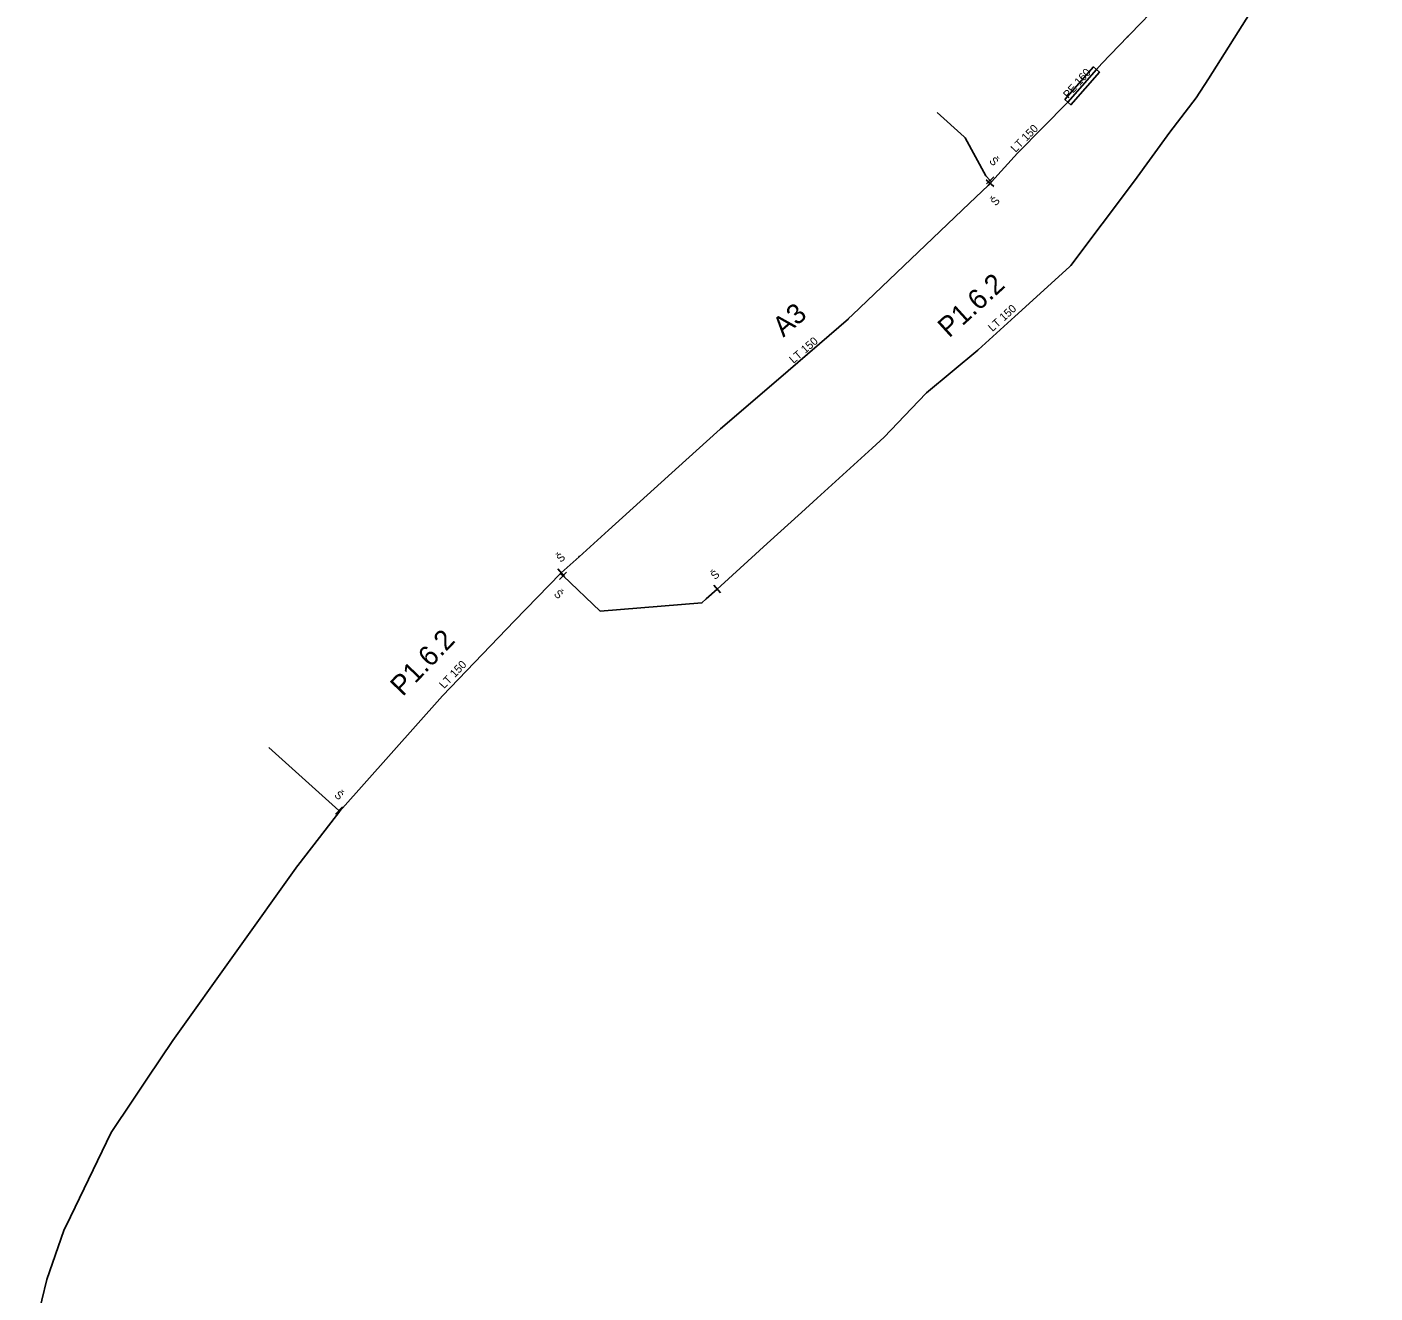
# Model space of a CAD drawing. Extents: x -569543 to -569081, y -1179531 to -1178244.
# Drawn here: x -569422.2 to -569085.2, y -1178887.5 to -1178571 of the extents above; entities that cross this region are included whole.
import ezdxf

# ---------------------------------------------------------------- set-up
doc = ezdxf.new("R2010")
doc.units = 0
for name, color, linetype in [('Vrstva 1', 7, 'Continuous'), ('Vrstva 15', 7, 'Continuous'), ('Vrstva 19', 7, 'Continuous'), ('Vrstva 28', 7, 'Continuous'), ('Vrstva 29', 7, 'Continuous'), ('Vrstva 35', 7, 'Continuous'), ('Vrstva 37', 7, 'Continuous')]:
    doc.layers.add(name, color=color, linetype=linetype)

# ---------------------------------------------------------------- blocks, each defined once
blk = doc.blocks.new('160')
at = {"layer": 'Vrstva 1'}
blk.add_circle((0, 0), 0.0458, dxfattribs=at)
blk = doc.blocks.new('147')
at = {"layer": 'Vrstva 1'}
blk.add_line((0, 1.27), (0, -1.27), dxfattribs=at)

msp = doc.modelspace()

# ---------------------------------------------------------------- linework, layer by layer
at = {"layer": 'Vrstva 15'}
for p, q in [((-569154.845, -1178581.632), (-569161.993, -1178589.749)), ((-569181.429, -1178610.037), (-569181.11, -1178609.67)), ((-569181.11, -1178609.67), (-569181.426, -1178609.336)), ((-569288.601, -1178707.419), (-569284.162, -1178703.404)), ((-569288.778, -1178707.579), (-569288.601, -1178707.419)), ((-569343.974, -1178767.046), (-569344.179, -1178766.861))]:
    msp.add_line(p, q, dxfattribs=at)
for points in [[(-569131.23, -1178557.07), (-569146.439, -1178572.804), (-569147.022, -1178573.407)], [(-569147.022, -1178573.407), (-569153.54, -1178580.15), (-569154.845, -1178581.632)], [(-569181.426, -1178609.336), (-569182.52, -1178608.18), (-569187.663, -1178598.668), (-569187.885, -1178598.468), (-569194.65562, -1178592.37263)], [(-569161.993, -1178589.749), (-569174.547, -1178602.502), (-569181.11, -1178609.67)], [(-569284.162, -1178703.404), (-569276.829, -1178696.773), (-569257.514, -1178679.306), (-569248.876, -1178671.495), (-569248.848, -1178671.471), (-569234.351, -1178659.002), (-569216.812, -1178643.918), (-569216.782, -1178643.889), (-569215.818, -1178642.969), (-569186.59, -1178615.064), (-569181.945, -1178610.63), (-569181.429, -1178610.037)], [(-569344.179, -1178766.861), (-569361.73731, -1178751.07335)]]:
    msp.add_lwpolyline(points, dxfattribs=at)
at = {"layer": 'Vrstva 19'}
msp.add_line((-569288.778, -1178707.579), (-569288.156, -1178708.174), dxfattribs=at)
for points in [[(-569126.848, -1178583.932), (-569115.399, -1178565.903), (-569109.69, -1178549.99), (-569107.811, -1178544.443), (-569102.14, -1178527.7), (-569102.141, -1178527.71), (-569099.966, -1178509.801), (-569099.96, -1178509.75), (-569098.39, -1178493.34), (-569093.92, -1178459.46), (-569093.676, -1178456.401), (-569091.39, -1178427.68), (-569087.77, -1178416.85), (-569087.76, -1178416.717), (-569087.461, -1178412.874), (-569085.259, -1178384.549), (-569085.217, -1178384.005)], [(-569249.688, -1178711.513), (-569248.737, -1178710.649), (-569237.136, -1178700.105), (-569228.597, -1178692.344), (-569224.653, -1178688.759), (-569210.881, -1178676.242), (-569207.93, -1178673.56), (-569201.051, -1178666.353), (-569197.394, -1178662.521), (-569197.355, -1178662.48), (-569184.461, -1178651.768), (-569184.397, -1178651.71), (-569175.229, -1178643.376), (-569161.596, -1178630.983), (-569161.23, -1178630.65), (-569153.398, -1178620.21), (-569145.308, -1178609.427), (-569145.31, -1178609.429), (-569136.519, -1178597.285), (-569136.511, -1178597.274), (-569129.884, -1178588.712), (-569126.848, -1178583.932)], [(-569343.974, -1178767.046), (-569318.258, -1178738.202), (-569300.301, -1178719.478), (-569288.778, -1178707.579)], [(-569288.156, -1178708.174), (-569278.88, -1178717.04), (-569253.48, -1178714.96), (-569252.384, -1178713.964), (-569249.688, -1178711.513)], [(-569422.16, -1178904.72), (-569417.19, -1178884.05), (-569412.92, -1178871.86), (-569411.292, -1178868.464), (-569401.15, -1178847.31), (-569395.719, -1178839.242), (-569392.043, -1178833.78), (-569385.697, -1178824.351), (-569385.667, -1178824.308), (-569354.502, -1178780.692), (-569354.456, -1178780.627), (-569347.644, -1178771.801), (-569343.974, -1178767.046)]]:
    msp.add_lwpolyline(points, dxfattribs=at)
at = {"layer": 'Vrstva 37'}
msp.add_lwpolyline([(-569162.744, -1178589.089), (-569155.595, -1178580.971), (-569154.095, -1178582.293), (-569161.243, -1178590.41), (-569162.744, -1178589.089)], dxfattribs=at)

# ---------------------------------------------------------------- block references
at = {"layer": 'Vrstva 29'}
for name, p, xscale, yscale, rotation in [('160', (-569147.022, -1178573.407), 0.999999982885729, 0.9999999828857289, -135), ('160', (-569154.845, -1178581.632), 0.9999999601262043, 0.9999999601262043, -131.99999877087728), ('160', (-569126.848, -1178583.932), 0.9999999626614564, 0.9999999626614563, -122.99999840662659), ('160', (-569161.993, -1178589.749), 0.9999999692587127, 0.9999999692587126, -133.99999919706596), ('147', (-569181.429, -1178610.037), 0.9999999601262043, 0.9999999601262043, -131.99999877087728), ('147', (-569181.426, -1178609.336), 0.9999999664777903, 0.9999999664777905, 132.99999806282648), ('160', (-569181.11, -1178609.67), 0.9999999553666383, 0.9999999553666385, 91.00000000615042), ('160', (-569284.162, -1178703.404), 0.9999999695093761, 0.9999999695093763, -138.9999986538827), ('147', (-569288.601, -1178707.419), 0.9999999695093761, 0.9999999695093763, -138.9999986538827), ('147', (-569288.156, -1178708.174), 0.9999999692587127, 0.9999999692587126, 136.00000080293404), ('147', (-569249.688, -1178711.513), 0.9999999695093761, 0.9999999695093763, -138.9999986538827), ('147', (-569344.179, -1178766.861), 0.9999999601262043, 0.9999999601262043, 138.0000012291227), ('160', (-569343.974, -1178767.046), 0.9999999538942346, 0.9999999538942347, -177.9999999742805)]:
    msp.add_blockref(name, p, dxfattribs=dict(at, xscale=xscale, yscale=yscale, rotation=rotation))
at = {"layer": 'Vrstva 29', "rotation": 180}
msp.add_blockref('160', (-569288.778, -1178707.579), dxfattribs=at)

# ---------------------------------------------------------------- texts
at = {"layer": 'Vrstva 28'}
for rotation, p in [(313.92, (-569181.807, -1178604.598)), (48.48, (-569180.008, -1178615.871)), (41.62, (-569288.756, -1178704.979)), (41.77, (-569250.184, -1178709.284)), (316.79, (-569290.612, -1178712.892)), (318.54, (-569345.494, -1178763.201))]:
    msp.add_text('Š', height=1.99999, rotation=rotation, dxfattribs=at).set_placement(p)
at = {"layer": 'Vrstva 35'}
for s, height, rotation, p in [('PE 160', 1.999992, 48.63, (-569161.89, -1178589.026)), ('LT 150', 1.999992, 45.45, (-569175.091, -1178602.485)), ('P1.6.2', 4.99998, 42.27, (-569191.686, -1178648.871)), ('A3', 4.99998, 40.7, (-569233.099, -1178648.694)), ('LT 150', 1.999992, 42.27, (-569180.846, -1178647.262)), ('LT 150', 1.999992, 40.7, (-569230.58, -1178655.232)), ('P1.6.2', 4.99998, 46.2, (-569328.242, -1178738.507)), ('LT 150', 1.999992, 46.2, (-569317.902, -1178736.537))]:
    msp.add_text(s, height=height, rotation=rotation, dxfattribs=at).set_placement(p)

doc.saveas('drawing.dxf')
